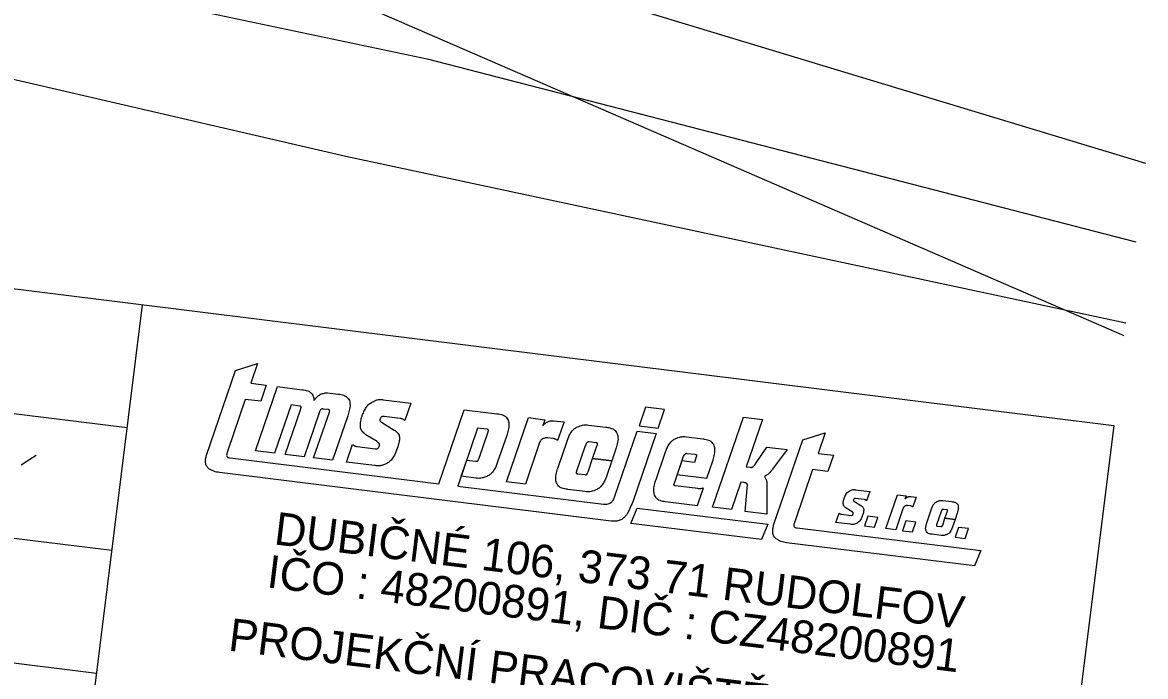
# Model space of a CAD drawing. Extents: x -804850 to -804680, y -1165160 to -1165081.
# Drawn here: x -804704.15 to -804691.08, y -1165145.59 to -1165137.98 of the extents above; entities that cross this region are included whole.
import ezdxf

# ---------------------------------------------------------------- set-up
doc = ezdxf.new("R2010")
doc.units = 0
for name, color, linetype in [('1_2000 - úřady', 7, 'Continuous'), ('LOGO TMS', 7, 'Continuous'), ('Rozpiska TMS', 7, 'Continuous'), ('Stsitu', 7, 'Continuous')]:
    doc.layers.add(name, color=color, linetype=linetype)

msp = doc.modelspace()

# ---------------------------------------------------------------- linework, layer by layer
at = {"layer": '1_2000 - úřady'}
for p, q in [((-804723.782, -1165140.1), (-804702.935, -1165142.693)), ((-804702.757, -1165141.264), (-804703.468, -1165146.98)), ((-804723.959, -1165141.529), (-804703.112, -1165144.122)), ((-804724.137, -1165142.958), (-804703.29, -1165145.551)), ((-804704.165, -1165143.127), (-804704.065, -1165143.061)), ((-804704.065, -1165143.061), (-804703.991, -1165143.016))]:
    msp.add_line(p, q, dxfattribs=at)
msp.add_lwpolyline([(-804723.604, -1165138.671), (-804691.451, -1165142.67), (-804692.162, -1165148.386), (-804724.315, -1165144.387)], close=True, dxfattribs=at)
at = {"layer": 'LOGO TMS'}
for p, q in [((-804702.01, -1165143.014), (-804701.673, -1165142.031)), ((-804701.673, -1165142.031), (-804701.415, -1165141.95)), ((-804701.415, -1165141.95), (-804701.494, -1165142.179)), ((-804701.494, -1165142.179), (-804701.314, -1165142.201)), ((-804701.44, -1165142.964), (-804701.183, -1165142.217)), ((-804701.314, -1165142.201), (-804701.379, -1165142.388)), ((-804701.183, -1165142.217), (-804700.899, -1165142.253)), ((-804700.601, -1165142.289), (-804700.479, -1165142.304)), ((-804701.558, -1165142.366), (-804701.762, -1165142.962)), ((-804701.379, -1165142.388), (-804701.558, -1165142.366)), ((-804701.026, -1165142.431), (-804701.219, -1165142.992)), ((-804700.928, -1165142.444), (-804701.026, -1165142.431)), ((-804699.952, -1165142.37), (-804699.63, -1165142.409)), ((-804699.63, -1165142.409), (-804699.7, -1165142.613)), ((-804701.096, -1165143.007), (-804700.913, -1165142.474)), ((-804700.7, -1165142.523), (-804700.875, -1165143.034)), ((-804700.763, -1165143.048), (-804700.58, -1165142.516)), ((-804700.595, -1165142.485), (-804700.654, -1165142.478)), ((-804700.364, -1165142.556), (-804700.542, -1165143.075)), ((-804699.755, -1165142.589), (-804699.944, -1165142.565)), ((-804699.306, -1165143.347), (-804699.011, -1165142.486)), ((-804699.011, -1165142.486), (-804698.631, -1165142.533)), ((-804696.901, -1165142.455), (-804696.975, -1165142.672)), ((-804696.68, -1165142.483), (-804696.901, -1165142.455)), ((-804696.754, -1165142.699), (-804696.68, -1165142.483)), ((-804699.973, -1165142.633), (-804699.825, -1165142.723)), ((-804698.52, -1165143.325), (-804698.264, -1165142.578)), ((-804698.264, -1165142.578), (-804698.071, -1165142.602)), ((-804698.071, -1165142.602), (-804698.095, -1165142.672)), ((-804697.969, -1165142.615), (-804697.849, -1165142.629)), ((-804697.849, -1165142.629), (-804697.924, -1165142.846)), ((-804697.563, -1165142.665), (-804697.362, -1165142.69)), ((-804696.975, -1165142.672), (-804696.754, -1165142.699)), ((-804696.121, -1165143.622), (-804695.761, -1165142.574)), ((-804695.761, -1165142.574), (-804695.54, -1165142.601)), ((-804695.54, -1165142.601), (-804695.729, -1165143.15)), ((-804700.024, -1165142.858), (-804700.154, -1165142.779)), ((-804698.854, -1165142.7), (-804699.085, -1165143.374)), ((-804698.747, -1165142.713), (-804698.854, -1165142.7)), ((-804698.838, -1165143.051), (-804698.732, -1165142.744)), ((-804698.516, -1165142.785), (-804698.622, -1165143.094)), ((-804697.979, -1165142.822), (-804698.037, -1165142.815)), ((-804697.252, -1165143.48), (-804696.997, -1165142.735)), ((-804696.776, -1165142.762), (-804697.049, -1165143.559)), ((-804696.997, -1165142.735), (-804696.776, -1165142.762)), ((-804696.232, -1165142.829), (-804696.425, -1165142.806)), ((-804695.068, -1165142.838), (-804694.81, -1165142.757)), ((-804694.81, -1165142.757), (-804694.892, -1165142.995)), ((-804700.381, -1165143.095), (-804700.31, -1165142.89)), ((-804700.255, -1165142.915), (-804700.045, -1165142.941)), ((-804698.133, -1165142.868), (-804698.299, -1165143.352)), ((-804697.919, -1165143.16), (-804697.813, -1165142.852)), ((-804697.602, -1165142.906), (-804697.703, -1165143.201)), ((-804697.478, -1165142.87), (-804697.556, -1165142.86)), ((-804697.516, -1165143.054), (-804697.463, -1165142.9)), ((-804697.247, -1165142.943), (-804697.294, -1165143.081)), ((-804695.62, -1165143.115), (-804695.487, -1165142.922)), ((-804695.487, -1165142.922), (-804695.252, -1165142.95)), ((-804695.252, -1165142.95), (-804695.422, -1165143.177)), ((-804695.409, -1165143.83), (-804695.068, -1165142.838)), ((-804701.735, -1165143.046), (-804699.306, -1165143.347)), ((-804701.219, -1165142.992), (-804701.44, -1165142.964)), ((-804700.875, -1165143.034), (-804701.096, -1165143.007)), ((-804700.542, -1165143.075), (-804700.763, -1165143.048)), ((-804699.046, -1165143.26), (-804698.981, -1165143.072)), ((-804698.981, -1165143.072), (-804698.876, -1165143.085)), ((-804697.569, -1165143.208), (-804697.516, -1165143.054)), ((-804697.516, -1165143.054), (-804697.294, -1165143.081)), ((-804697.294, -1165143.081), (-804697.516, -1165143.054)), ((-804697.294, -1165143.081), (-804697.352, -1165143.251)), ((-804696.676, -1165142.993), (-804696.782, -1165143.301)), ((-804696.565, -1165143.342), (-804696.462, -1165143.04)), ((-804696.476, -1165143.081), (-804696.531, -1165143.24)), ((-804696.332, -1165143.099), (-804696.476, -1165143.081)), ((-804696.416, -1165142.994), (-804696.325, -1165143.005)), ((-804696.31, -1165143.036), (-804696.332, -1165143.099)), ((-804696.186, -1165143.283), (-804696.117, -1165143.083)), ((-804694.892, -1165142.995), (-804694.713, -1165143.017)), ((-804694.713, -1165143.017), (-804694.777, -1165143.204)), ((-804697.301, -1165143.782), (-804701.859, -1165143.218)), ((-804700.056, -1165143.135), (-804700.381, -1165143.095)), ((-804695.729, -1165143.15), (-804695.681, -1165143.156)), ((-804694.956, -1165143.182), (-804695.16, -1165143.778)), ((-804694.777, -1165143.204), (-804694.956, -1165143.182)), ((-804698.873, -1165143.282), (-804699.046, -1165143.26)), ((-804698.299, -1165143.352), (-804698.52, -1165143.325)), ((-804697.688, -1165143.232), (-804697.607, -1165143.242)), ((-804696.531, -1165143.24), (-804696.186, -1165143.283)), ((-804695.79, -1165143.33), (-804695.9, -1165143.649)), ((-804695.752, -1165143.335), (-804695.79, -1165143.33)), ((-804699.085, -1165143.374), (-804697.388, -1165143.584)), ((-804697.603, -1165143.439), (-804697.805, -1165143.414)), ((-804696.293, -1165143.404), (-804696.551, -1165143.372)), ((-804696.295, -1165143.6), (-804696.224, -1165143.395)), ((-804695.74, -1165143.669), (-804695.717, -1165143.405)), ((-804695.488, -1165143.388), (-804695.49, -1165143.7)), ((-804694.459, -1165143.417), (-804694.291, -1165143.438)), ((-804694.291, -1165143.438), (-804694.327, -1165143.545)), ((-804694.104, -1165143.87), (-804693.969, -1165143.477)), ((-804693.969, -1165143.477), (-804693.868, -1165143.49)), ((-804696.667, -1165143.554), (-804696.295, -1165143.6)), ((-804694.47, -1165143.555), (-804694.393, -1165143.602)), ((-804694.356, -1165143.532), (-804694.455, -1165143.52)), ((-804693.868, -1165143.49), (-804693.881, -1165143.527)), ((-804693.819, -1165143.605), (-804693.85, -1165143.601)), ((-804693.814, -1165143.497), (-804693.752, -1165143.504)), ((-804693.752, -1165143.504), (-804693.791, -1165143.618)), ((-804693.439, -1165143.543), (-804693.334, -1165143.556)), ((-804697.07, -1165143.81), (-804696.996, -1165143.632)), ((-804696.996, -1165143.632), (-804695.475, -1165143.82)), ((-804695.9, -1165143.649), (-804696.121, -1165143.622)), ((-804695.49, -1165143.7), (-804695.74, -1165143.669)), ((-804694.684, -1165143.798), (-804694.648, -1165143.69)), ((-804694.619, -1165143.703), (-804694.508, -1165143.717)), ((-804694.497, -1165143.673), (-804694.565, -1165143.632)), ((-804694.314, -1165143.725), (-804694.353, -1165143.839)), ((-804694.198, -1165143.74), (-804694.314, -1165143.725)), ((-804694.237, -1165143.853), (-804694.198, -1165143.74)), ((-804693.9, -1165143.629), (-804693.988, -1165143.884)), ((-804693.626, -1165143.803), (-804693.571, -1165143.641)), ((-804693.459, -1165143.669), (-804693.513, -1165143.824)), ((-804693.394, -1165143.651), (-804693.435, -1165143.646)), ((-804693.415, -1165143.747), (-804693.387, -1165143.667)), ((-804693.273, -1165143.689), (-804693.298, -1165143.762)), ((-804695.549, -1165143.998), (-804697.07, -1165143.81)), ((-804695.475, -1165143.82), (-804695.549, -1165143.998)), ((-804695.134, -1165143.862), (-804692.999, -1165144.126)), ((-804694.514, -1165143.819), (-804694.684, -1165143.798)), ((-804694.353, -1165143.839), (-804694.237, -1165143.853)), ((-804693.988, -1165143.884), (-804694.104, -1165143.87)), ((-804693.87, -1165143.78), (-804693.909, -1165143.894)), ((-804693.754, -1165143.794), (-804693.87, -1165143.78)), ((-804693.793, -1165143.908), (-804693.754, -1165143.794)), ((-804693.505, -1165143.84), (-804693.463, -1165143.846)), ((-804693.442, -1165143.828), (-804693.415, -1165143.747)), ((-804693.415, -1165143.747), (-804693.298, -1165143.762)), ((-804693.298, -1165143.762), (-804693.415, -1165143.747)), ((-804693.298, -1165143.762), (-804693.329, -1165143.851)), ((-804693.257, -1165143.856), (-804693.296, -1165143.969)), ((-804693.141, -1165143.87), (-804693.257, -1165143.856)), ((-804693.18, -1165143.984), (-804693.141, -1165143.87)), ((-804693.909, -1165143.894), (-804693.793, -1165143.908)), ((-804693.46, -1165143.949), (-804693.566, -1165143.936)), ((-804693.296, -1165143.969), (-804693.18, -1165143.984)), ((-804693.073, -1165144.304), (-804695.258, -1165144.034)), ((-804692.999, -1165144.126), (-804693.073, -1165144.304))]:
    msp.add_line(p, q, dxfattribs=at)
for points in [[(-804700.899, -1165142.252), (-804700.881, -1165142.255), (-804700.846, -1165142.262), (-804700.819, -1165142.272), (-804700.792, -1165142.292), (-804700.763, -1165142.342), (-804700.76, -1165142.365), (-804700.759, -1165142.375), (-804700.758, -1165142.38)], [(-804700.758, -1165142.38), (-804700.733, -1165142.348), (-804700.709, -1165142.325), (-804700.679, -1165142.307), (-804700.66, -1165142.299), (-804700.637, -1165142.293), (-804700.62, -1165142.29), (-804700.601, -1165142.289)], [(-804700.479, -1165142.304), (-804700.461, -1165142.307), (-804700.426, -1165142.314), (-804700.399, -1165142.324), (-804700.372, -1165142.344), (-804700.343, -1165142.394), (-804700.34, -1165142.416), (-804700.339, -1165142.426), (-804700.348, -1165142.497), (-804700.356, -1165142.528), (-804700.364, -1165142.556)], [(-804700.154, -1165142.779), (-804700.18, -1165142.757), (-804700.2, -1165142.736), (-804700.216, -1165142.698), (-804700.218, -1165142.657), (-804700.214, -1165142.618), (-804700.2, -1165142.562), (-804700.184, -1165142.521), (-804700.158, -1165142.472), (-804700.128, -1165142.431), (-804700.091, -1165142.402), (-804700.044, -1165142.378), (-804700.009, -1165142.369), (-804699.976, -1165142.367), (-804699.952, -1165142.37)], [(-804700.913, -1165142.474), (-804700.911, -1165142.468), (-804700.91, -1165142.46), (-804700.91, -1165142.453), (-804700.913, -1165142.448), (-804700.919, -1165142.445), (-804700.928, -1165142.444)], [(-804700.654, -1165142.478), (-804700.66, -1165142.477), (-804700.666, -1165142.478), (-804700.674, -1165142.481), (-804700.683, -1165142.489), (-804700.689, -1165142.498), (-804700.7, -1165142.523)], [(-804700.58, -1165142.516), (-804700.578, -1165142.509), (-804700.576, -1165142.501), (-804700.577, -1165142.494), (-804700.58, -1165142.489), (-804700.586, -1165142.486), (-804700.595, -1165142.485)], [(-804699.944, -1165142.565), (-804699.959, -1165142.565), (-804699.968, -1165142.568), (-804699.978, -1165142.574), (-804699.985, -1165142.584), (-804699.99, -1165142.596), (-804699.992, -1165142.609), (-804699.989, -1165142.619), (-804699.982, -1165142.626), (-804699.973, -1165142.633)], [(-804698.631, -1165142.533), (-804698.612, -1165142.535), (-804698.578, -1165142.542), (-804698.55, -1165142.552), (-804698.524, -1165142.572), (-804698.495, -1165142.622), (-804698.491, -1165142.645), (-804698.49, -1165142.655), (-804698.5, -1165142.725), (-804698.507, -1165142.756), (-804698.516, -1165142.785)], [(-804699.7, -1165142.613), (-804699.712, -1165142.604), (-804699.724, -1165142.597), (-804699.732, -1165142.594), (-804699.745, -1165142.59), (-804699.755, -1165142.589)], [(-804698.095, -1165142.672), (-804698.079, -1165142.655), (-804698.066, -1165142.643), (-804698.047, -1165142.631), (-804698.031, -1165142.623), (-804698.009, -1165142.617), (-804697.991, -1165142.614), (-804697.969, -1165142.615)], [(-804697.813, -1165142.852), (-804697.798, -1165142.808), (-804697.776, -1165142.764), (-804697.746, -1165142.724), (-804697.717, -1165142.699), (-804697.678, -1165142.68), (-804697.646, -1165142.669), (-804697.619, -1165142.664), (-804697.595, -1165142.662), (-804697.563, -1165142.665)], [(-804697.362, -1165142.69), (-804697.344, -1165142.692), (-804697.309, -1165142.699), (-804697.281, -1165142.709), (-804697.255, -1165142.729), (-804697.226, -1165142.779), (-804697.223, -1165142.802), (-804697.221, -1165142.812), (-804697.231, -1165142.882), (-804697.238, -1165142.913), (-804697.247, -1165142.943)], [(-804699.825, -1165142.723), (-804699.815, -1165142.729), (-804699.796, -1165142.746), (-804699.782, -1165142.761), (-804699.769, -1165142.783), (-804699.764, -1165142.801), (-804699.766, -1165142.848), (-804699.779, -1165142.9), (-804699.805, -1165142.976), (-804699.823, -1165143.016), (-804699.852, -1165143.061), (-804699.893, -1165143.099), (-804699.93, -1165143.12), (-804699.969, -1165143.134), (-804700.01, -1165143.139), (-804700.056, -1165143.135)], [(-804698.732, -1165142.744), (-804698.73, -1165142.737), (-804698.728, -1165142.73), (-804698.729, -1165142.723), (-804698.732, -1165142.718), (-804698.738, -1165142.715), (-804698.747, -1165142.713)], [(-804698.037, -1165142.815), (-804698.051, -1165142.814), (-804698.065, -1165142.815), (-804698.083, -1165142.82), (-804698.098, -1165142.826), (-804698.11, -1165142.834), (-804698.124, -1165142.849), (-804698.133, -1165142.868)], [(-804697.924, -1165142.846), (-804697.936, -1165142.837), (-804697.948, -1165142.83), (-804697.955, -1165142.827), (-804697.965, -1165142.824), (-804697.979, -1165142.822)], [(-804696.425, -1165142.806), (-804696.457, -1165142.802), (-804696.482, -1165142.804), (-804696.509, -1165142.81), (-804696.541, -1165142.821), (-804696.579, -1165142.84), (-804696.608, -1165142.865), (-804696.639, -1165142.905), (-804696.66, -1165142.949), (-804696.676, -1165142.993)], [(-804700.31, -1165142.89), (-804700.299, -1165142.899), (-804700.286, -1165142.906), (-804700.279, -1165142.909), (-804700.265, -1165142.913), (-804700.255, -1165142.915)], [(-804700.045, -1165142.941), (-804700.03, -1165142.942), (-804700.02, -1165142.938), (-804700.008, -1165142.927), (-804700.001, -1165142.913), (-804699.996, -1165142.895), (-804699.997, -1165142.883), (-804700.002, -1165142.875), (-804700.014, -1165142.866), (-804700.024, -1165142.858)], [(-804697.556, -1165142.86), (-804697.561, -1165142.86), (-804697.568, -1165142.861), (-804697.576, -1165142.864), (-804697.585, -1165142.872), (-804697.591, -1165142.881), (-804697.602, -1165142.906)], [(-804697.463, -1165142.9), (-804697.461, -1165142.894), (-804697.459, -1165142.887), (-804697.46, -1165142.88), (-804697.463, -1165142.874), (-804697.469, -1165142.872), (-804697.478, -1165142.87)], [(-804696.117, -1165143.083), (-804696.109, -1165143.053), (-804696.101, -1165143.022), (-804696.092, -1165142.951), (-804696.093, -1165142.941), (-804696.096, -1165142.919), (-804696.125, -1165142.869), (-804696.151, -1165142.849), (-804696.179, -1165142.839), (-804696.214, -1165142.832), (-804696.232, -1165142.829)], [(-804701.859, -1165143.218), (-804701.925, -1165143.202), (-804701.96, -1165143.186), (-804701.989, -1165143.167), (-804702.012, -1165143.135), (-804702.022, -1165143.088), (-804702.02, -1165143.056), (-804702.01, -1165143.014)], [(-804701.762, -1165142.962), (-804701.769, -1165142.983), (-804701.775, -1165143.004), (-804701.775, -1165143.024), (-804701.766, -1165143.037), (-804701.753, -1165143.043), (-804701.735, -1165143.046)], [(-804698.876, -1165143.085), (-804698.863, -1165143.086), (-804698.853, -1165143.082), (-804698.847, -1165143.072), (-804698.843, -1165143.063), (-804698.838, -1165143.051)], [(-804696.462, -1165143.04), (-804696.451, -1165143.014), (-804696.445, -1165143.006), (-804696.435, -1165142.998), (-804696.428, -1165142.994), (-804696.421, -1165142.994), (-804696.416, -1165142.994)], [(-804696.325, -1165143.005), (-804696.316, -1165143.007), (-804696.31, -1165143.01), (-804696.307, -1165143.015), (-804696.306, -1165143.022), (-804696.308, -1165143.029), (-804696.31, -1165143.036)], [(-804698.622, -1165143.094), (-804698.638, -1165143.138), (-804698.66, -1165143.182), (-804698.69, -1165143.222), (-804698.719, -1165143.247), (-804698.758, -1165143.266), (-804698.79, -1165143.277), (-804698.817, -1165143.283), (-804698.841, -1165143.285), (-804698.873, -1165143.282)], [(-804697.805, -1165143.414), (-804697.823, -1165143.411), (-804697.857, -1165143.404), (-804697.885, -1165143.395), (-804697.912, -1165143.374), (-804697.94, -1165143.324), (-804697.944, -1165143.302), (-804697.945, -1165143.292), (-804697.935, -1165143.221), (-804697.928, -1165143.19), (-804697.919, -1165143.16)], [(-804697.703, -1165143.201), (-804697.705, -1165143.208), (-804697.707, -1165143.215), (-804697.707, -1165143.222), (-804697.704, -1165143.227), (-804697.697, -1165143.23), (-804697.688, -1165143.232)], [(-804697.607, -1165143.242), (-804697.594, -1165143.243), (-804697.584, -1165143.239), (-804697.578, -1165143.229), (-804697.574, -1165143.22), (-804697.569, -1165143.208)], [(-804695.681, -1165143.156), (-804695.667, -1165143.157), (-804695.661, -1165143.156), (-804695.653, -1165143.152), (-804695.646, -1165143.146), (-804695.624, -1165143.121), (-804695.62, -1165143.115)], [(-804695.422, -1165143.177), (-804695.444, -1165143.207), (-804695.46, -1165143.225), (-804695.477, -1165143.239), (-804695.492, -1165143.249), (-804695.514, -1165143.262)], [(-804697.352, -1165143.251), (-804697.368, -1165143.295), (-804697.39, -1165143.339), (-804697.42, -1165143.379), (-804697.449, -1165143.404), (-804697.488, -1165143.423), (-804697.52, -1165143.434), (-804697.547, -1165143.44), (-804697.571, -1165143.442), (-804697.603, -1165143.439)], [(-804696.782, -1165143.301), (-804696.791, -1165143.331), (-804696.798, -1165143.362), (-804696.808, -1165143.432), (-804696.806, -1165143.442), (-804696.803, -1165143.465), (-804696.774, -1165143.515), (-804696.748, -1165143.535), (-804696.72, -1165143.545), (-804696.685, -1165143.552), (-804696.667, -1165143.554)], [(-804696.551, -1165143.372), (-804696.56, -1165143.371), (-804696.566, -1165143.368), (-804696.569, -1165143.363), (-804696.569, -1165143.356), (-804696.568, -1165143.348), (-804696.565, -1165143.342)], [(-804695.717, -1165143.405), (-804695.715, -1165143.375), (-804695.716, -1165143.354), (-804695.721, -1165143.346), (-804695.729, -1165143.34), (-804695.736, -1165143.337), (-804695.752, -1165143.335)], [(-804695.514, -1165143.262), (-804695.506, -1165143.279), (-804695.499, -1165143.295), (-804695.494, -1165143.309), (-804695.49, -1165143.33), (-804695.488, -1165143.359), (-804695.488, -1165143.388)], [(-804697.388, -1165143.584), (-804697.364, -1165143.586), (-804697.336, -1165143.582), (-804697.315, -1165143.572), (-804697.294, -1165143.557), (-804697.27, -1165143.524), (-804697.262, -1165143.503), (-804697.252, -1165143.48)], [(-804696.224, -1165143.395), (-804696.235, -1165143.4), (-804696.25, -1165143.405), (-804696.271, -1165143.407), (-804696.293, -1165143.404)], [(-804694.565, -1165143.632), (-804694.579, -1165143.62), (-804694.59, -1165143.609), (-804694.598, -1165143.589), (-804694.599, -1165143.568), (-804694.597, -1165143.547), (-804694.59, -1165143.518), (-804694.581, -1165143.496), (-804694.568, -1165143.471), (-804694.552, -1165143.449), (-804694.532, -1165143.434), (-804694.508, -1165143.421), (-804694.489, -1165143.416), (-804694.472, -1165143.415), (-804694.459, -1165143.417)], [(-804697.049, -1165143.559), (-804697.083, -1165143.637), (-804697.102, -1165143.676), (-804697.122, -1165143.708), (-804697.142, -1165143.734), (-804697.178, -1165143.763), (-804697.224, -1165143.779), (-804697.268, -1165143.785), (-804697.301, -1165143.782)], [(-804694.393, -1165143.602), (-804694.387, -1165143.605), (-804694.377, -1165143.614), (-804694.37, -1165143.622), (-804694.363, -1165143.634), (-804694.361, -1165143.643), (-804694.362, -1165143.668), (-804694.368, -1165143.695), (-804694.382, -1165143.735), (-804694.392, -1165143.756), (-804694.407, -1165143.78), (-804694.428, -1165143.799), (-804694.448, -1165143.811), (-804694.468, -1165143.818), (-804694.49, -1165143.821), (-804694.514, -1165143.819)], [(-804694.455, -1165143.52), (-804694.463, -1165143.519), (-804694.468, -1165143.521), (-804694.473, -1165143.524), (-804694.477, -1165143.529), (-804694.479, -1165143.536), (-804694.481, -1165143.543), (-804694.479, -1165143.548), (-804694.475, -1165143.552), (-804694.47, -1165143.555)], [(-804694.327, -1165143.545), (-804694.333, -1165143.54), (-804694.34, -1165143.536), (-804694.344, -1165143.535), (-804694.351, -1165143.533), (-804694.356, -1165143.532)], [(-804693.85, -1165143.601), (-804693.858, -1165143.601), (-804693.865, -1165143.602), (-804693.874, -1165143.604), (-804693.882, -1165143.607), (-804693.888, -1165143.612), (-804693.896, -1165143.62), (-804693.9, -1165143.629)], [(-804693.881, -1165143.527), (-804693.872, -1165143.517), (-804693.865, -1165143.512), (-804693.855, -1165143.505), (-804693.847, -1165143.501), (-804693.835, -1165143.498), (-804693.826, -1165143.496), (-804693.814, -1165143.497)], [(-804693.791, -1165143.618), (-804693.797, -1165143.613), (-804693.803, -1165143.61), (-804693.807, -1165143.608), (-804693.812, -1165143.606), (-804693.819, -1165143.605)], [(-804693.571, -1165143.641), (-804693.562, -1165143.618), (-804693.551, -1165143.595), (-804693.535, -1165143.574), (-804693.52, -1165143.561), (-804693.5, -1165143.551), (-804693.483, -1165143.545), (-804693.469, -1165143.542), (-804693.456, -1165143.541), (-804693.439, -1165143.543)], [(-804693.334, -1165143.556), (-804693.324, -1165143.557), (-804693.306, -1165143.561), (-804693.291, -1165143.566), (-804693.277, -1165143.576), (-804693.262, -1165143.603), (-804693.261, -1165143.615), (-804693.26, -1165143.62), (-804693.265, -1165143.657), (-804693.269, -1165143.673), (-804693.273, -1165143.689)], [(-804694.648, -1165143.69), (-804694.641, -1165143.695), (-804694.635, -1165143.698), (-804694.631, -1165143.7), (-804694.624, -1165143.702), (-804694.619, -1165143.703)], [(-804694.508, -1165143.717), (-804694.5, -1165143.717), (-804694.495, -1165143.715), (-804694.489, -1165143.709), (-804694.485, -1165143.702), (-804694.482, -1165143.693), (-804694.483, -1165143.687), (-804694.485, -1165143.682), (-804694.492, -1165143.677), (-804694.497, -1165143.673)], [(-804693.435, -1165143.646), (-804693.438, -1165143.645), (-804693.442, -1165143.646), (-804693.446, -1165143.647), (-804693.451, -1165143.652), (-804693.454, -1165143.656), (-804693.46, -1165143.669)], [(-804693.387, -1165143.667), (-804693.386, -1165143.663), (-804693.385, -1165143.659), (-804693.385, -1165143.656), (-804693.387, -1165143.653), (-804693.39, -1165143.651), (-804693.394, -1165143.651)], [(-804695.258, -1165144.034), (-804695.323, -1165144.018), (-804695.358, -1165144.002), (-804695.387, -1165143.982), (-804695.41, -1165143.951), (-804695.42, -1165143.904), (-804695.418, -1165143.872), (-804695.409, -1165143.83)], [(-804695.16, -1165143.778), (-804695.168, -1165143.799), (-804695.173, -1165143.82), (-804695.173, -1165143.84), (-804695.165, -1165143.853), (-804695.151, -1165143.859), (-804695.134, -1165143.862)], [(-804693.566, -1165143.936), (-804693.576, -1165143.935), (-804693.594, -1165143.931), (-804693.608, -1165143.926), (-804693.622, -1165143.915), (-804693.637, -1165143.889), (-804693.639, -1165143.877), (-804693.64, -1165143.872), (-804693.635, -1165143.835), (-804693.631, -1165143.819), (-804693.626, -1165143.803)], [(-804693.513, -1165143.824), (-804693.514, -1165143.828), (-804693.515, -1165143.832), (-804693.515, -1165143.836), (-804693.513, -1165143.838), (-804693.51, -1165143.84), (-804693.505, -1165143.84)], [(-804693.463, -1165143.846), (-804693.455, -1165143.846), (-804693.45, -1165143.844), (-804693.447, -1165143.839), (-804693.445, -1165143.834), (-804693.442, -1165143.828)], [(-804693.329, -1165143.851), (-804693.337, -1165143.874), (-804693.348, -1165143.897), (-804693.364, -1165143.918), (-804693.379, -1165143.931), (-804693.4, -1165143.941), (-804693.417, -1165143.947), (-804693.431, -1165143.95), (-804693.444, -1165143.951), (-804693.46, -1165143.949)]]:
    msp.add_spline(points, degree=3, dxfattribs=at)
at = {"layer": 'Stsitu'}
for p, q in [((-804691.33, -1165141.627), (-804728.07, -1165125.68)), ((-804724.802, -1165133.057), (-804699.443, -1165138.401)), ((-804724.988, -1165133.826), (-804700.388, -1165139.537)), ((-804700.35, -1165136.808), (-804691.081, -1165139.617)), ((-804699.443, -1165138.401), (-804691.194, -1165140.533)), ((-804700.388, -1165139.537), (-804691.311, -1165141.476))]:
    msp.add_line(p, q, dxfattribs=at)

# ---------------------------------------------------------------- texts
at = {"layer": 'Rozpiska TMS'}
for s, p in [('DUBIČNÉ 106, 373 71 RUDOLFOV', (-804701.234, -1165144.052)), ('IČO : 48200891, DIČ : CZ48200891', (-804701.318, -1165144.552)), ('PROJEKČNÍ PRACOVIŠTĚ PLZEŇ', (-804701.766, -1165145.288))]:
    msp.add_text(s, height=0.38016, rotation=352.9874, dxfattribs=at).set_placement(p)

doc.saveas('drawing.dxf')
